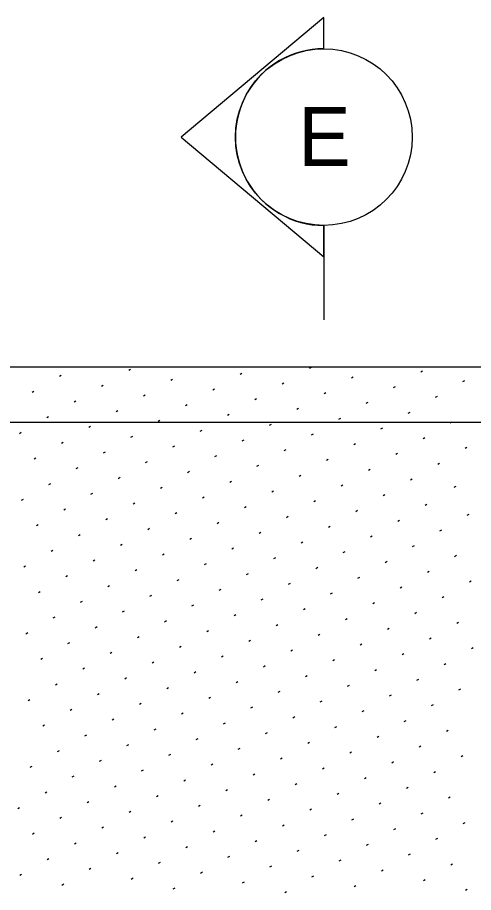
# Model space of a CAD drawing. Extents: x 99862 to 104211, y 98939 to 105076.
# Drawn here: x 101684.2 to 101839, y 104085.1 to 104382.1 of the extents above; entities that cross this region are included whole.
import ezdxf

# ---------------------------------------------------------------- set-up
doc = ezdxf.new("R2010")
doc.units = 0
for name, color, linetype in [('Level 1', 7, 'Continuous'), ('Level 20', 7, 'Continuous'), ('Level 3', 7, 'Continuous'), ('Level 6', 7, 'Continuous'), ('Level 9', 7, 'Continuous')]:
    doc.layers.add(name, color=color, linetype=linetype)

msp = doc.modelspace()

# ---------------------------------------------------------------- linework, layer by layer
at = {"layer": 'Level 1'}
msp.add_line((101394.64, 104263.53), (102106.49, 104263.53), dxfattribs=at)
at = {"layer": 'Level 3'}
for p, q in [((101783.3, 104263.12), (101783.9, 104263.47)), ((101698.42, 104260.31), (101699.03, 104260.66)), ((101721.96, 104262.35), (101722.56, 104262.7)), ((101759.76, 104261.08), (101760.37, 104261.43)), ((101797.56, 104259.81), (101798.17, 104260.16)), ((101821.1, 104261.85), (101821.7, 104262.2)), ((101712.69, 104257), (101713.3, 104257.35)), ((101736.22, 104259.04), (101736.83, 104259.39)), ((101774.03, 104257.77), (101774.63, 104258.12)), ((101811.83, 104256.5), (101812.44, 104256.85)), ((101835.37, 104258.54), (101835.97, 104258.89)), ((101689.15, 104254.96), (101689.76, 104255.31)), ((101726.96, 104253.69), (101727.56, 104254.04)), ((101750.49, 104255.73), (101751.1, 104256.08)), ((101788.3, 104254.46), (101788.9, 104254.81)), ((101703.42, 104251.65), (101704.03, 104252)), ((101764.76, 104252.42), (101765.37, 104252.77)), ((101802.56, 104251.15), (101803.17, 104251.5)), ((101826.1, 104253.19), (101826.7, 104253.54)), ((101717.69, 104248.34), (101718.3, 104248.69)), ((101741.22, 104250.38), (101741.83, 104250.73)), ((101779.03, 104249.11), (101779.63, 104249.46)), ((101816.83, 104247.84), (101817.44, 104248.19)), ((101694.15, 104246.3), (101694.76, 104246.65)), ((101731.96, 104245.03), (101732.56, 104245.38)), ((101755.49, 104247.07), (101756.1, 104247.42)), ((101793.3, 104245.8), (101793.9, 104246.15)), ((101708.42, 104242.99), (101709.03, 104243.34)), ((101746.22, 104241.72), (101746.83, 104242.07)), ((101769.76, 104243.76), (101770.37, 104244.11)), ((101807.56, 104242.49), (101808.17, 104242.84)), ((101831.1, 104244.53), (101831.7, 104244.88)), ((101684.89, 104240.95), (101685.49, 104241.3)), ((101722.69, 104239.68), (101723.3, 104240.03)), ((101784.03, 104240.45), (101784.63, 104240.8)), ((101821.83, 104239.18), (101822.44, 104239.53)), ((101699.15, 104237.64), (101699.76, 104237.99)), ((101736.96, 104236.37), (101737.56, 104236.72)), ((101760.49, 104238.41), (101761.1, 104238.76)), ((101798.3, 104237.14), (101798.9, 104237.49)), ((101836.1, 104235.87), (101836.7, 104236.22)), ((101713.42, 104234.33), (101714.03, 104234.68)), ((101751.22, 104233.06), (101751.83, 104233.41)), ((101774.76, 104235.1), (101775.37, 104235.45)), ((101812.56, 104233.83), (101813.17, 104234.18)), ((101689.89, 104232.29), (101690.49, 104232.64)), ((101727.69, 104231.02), (101728.3, 104231.37)), ((101765.49, 104229.75), (101766.1, 104230.1)), ((101789.03, 104231.79), (101789.63, 104232.14)), ((101826.83, 104230.52), (101827.44, 104230.87)), ((101704.15, 104228.98), (101704.76, 104229.33)), ((101741.96, 104227.71), (101742.56, 104228.06)), ((101803.3, 104228.48), (101803.9, 104228.83)), ((101718.42, 104225.67), (101719.03, 104226.02)), ((101756.22, 104224.4), (101756.83, 104224.75)), ((101779.76, 104226.44), (101780.37, 104226.79)), ((101817.56, 104225.17), (101818.17, 104225.52)), ((101694.89, 104223.62), (101695.49, 104223.97)), ((101732.69, 104222.36), (101733.3, 104222.71)), ((101770.49, 104221.09), (101771.1, 104221.44)), ((101794.03, 104223.13), (101794.63, 104223.48)), ((101832.46, 104222.7), (101833.07, 104223.05)), ((101685.62, 104218.27), (101686.22, 104218.62)), ((101709.15, 104220.32), (101709.76, 104220.67)), ((101746.96, 104219.05), (101747.56, 104219.4)), ((101808.3, 104219.82), (101808.9, 104220.17)), ((101699.89, 104214.96), (101700.49, 104215.31)), ((101723.42, 104217.01), (101724.03, 104217.36)), ((101761.22, 104215.74), (101761.83, 104216.09)), ((101784.76, 104217.78), (101785.37, 104218.13)), ((101822.56, 104216.51), (101823.17, 104216.86)), ((101737.69, 104213.7), (101738.3, 104214.05)), ((101775.49, 104212.43), (101776.1, 104212.78)), ((101799.03, 104214.47), (101799.63, 104214.82)), ((101836.83, 104213.2), (101837.44, 104213.55)), ((101690.62, 104209.61), (101691.22, 104209.96)), ((101714.15, 104211.65), (101714.76, 104212)), ((101751.96, 104210.39), (101752.56, 104210.74)), ((101789.76, 104209.12), (101790.37, 104209.47)), ((101813.3, 104211.16), (101813.9, 104211.51)), ((101704.89, 104206.3), (101705.49, 104206.65)), ((101728.42, 104208.35), (101729.03, 104208.7)), ((101766.22, 104207.08), (101766.83, 104207.43)), ((101827.56, 104207.85), (101828.17, 104208.2)), ((101742.69, 104205.04), (101743.3, 104205.39)), ((101780.49, 104203.77), (101781.1, 104204.12)), ((101804.03, 104205.81), (101804.63, 104206.16)), ((101695.62, 104200.95), (101696.22, 104201.3)), ((101719.15, 104202.99), (101719.76, 104203.34)), ((101756.96, 104201.73), (101757.56, 104202.08)), ((101794.76, 104200.46), (101795.37, 104200.81)), ((101818.3, 104202.5), (101818.9, 104202.85)), ((101709.89, 104197.64), (101710.49, 104197.99)), ((101733.42, 104199.69), (101734.03, 104200.04)), ((101771.22, 104198.42), (101771.83, 104198.77)), ((101809.03, 104197.15), (101809.63, 104197.5)), ((101832.56, 104199.19), (101833.17, 104199.54)), ((101686.35, 104195.6), (101686.96, 104195.95)), ((101724.15, 104194.33), (101724.76, 104194.68)), ((101747.69, 104196.38), (101748.3, 104196.73)), ((101785.49, 104195.11), (101786.1, 104195.46)), ((101700.62, 104192.29), (101701.22, 104192.64)), ((101761.96, 104193.07), (101762.56, 104193.42)), ((101799.76, 104191.8), (101800.37, 104192.15)), ((101823.3, 104193.84), (101823.9, 104194.19)), ((101714.89, 104188.98), (101715.49, 104189.33)), ((101738.42, 104191.02), (101739.03, 104191.37)), ((101776.22, 104189.76), (101776.83, 104190.11)), ((101814.03, 104188.49), (101814.63, 104188.84)), ((101837.56, 104190.53), (101838.17, 104190.88)), ((101691.35, 104186.94), (101691.96, 104187.29)), ((101729.15, 104185.67), (101729.76, 104186.02)), ((101752.69, 104187.72), (101753.3, 104188.07)), ((101790.49, 104186.45), (101791.1, 104186.8)), ((101828.3, 104185.18), (101828.9, 104185.53)), ((101705.62, 104183.63), (101706.22, 104183.98)), ((101743.42, 104182.36), (101744.03, 104182.71)), ((101766.96, 104184.41), (101767.56, 104184.76)), ((101804.76, 104183.14), (101805.37, 104183.49)), ((101719.89, 104180.32), (101720.49, 104180.67)), ((101781.22, 104181.1), (101781.83, 104181.45)), ((101819.03, 104179.83), (101819.63, 104180.18)), ((101696.35, 104178.28), (101696.96, 104178.63)), ((101734.15, 104177.01), (101734.76, 104177.36)), ((101757.69, 104179.06), (101758.3, 104179.41)), ((101795.49, 104177.79), (101796.1, 104178.14)), ((101833.3, 104176.52), (101833.9, 104176.87)), ((101710.62, 104174.97), (101711.22, 104175.32)), ((101748.42, 104173.7), (101749.03, 104174.05)), ((101771.96, 104175.75), (101772.56, 104176.1)), ((101809.76, 104174.48), (101810.37, 104174.83)), ((101687.08, 104172.93), (101687.69, 104173.28)), ((101724.89, 104171.66), (101725.49, 104172.01)), ((101762.69, 104170.39), (101763.3, 104170.74)), ((101786.22, 104172.44), (101786.83, 104172.79)), ((101824.03, 104171.17), (101824.63, 104171.52)), ((101701.35, 104169.62), (101701.96, 104169.97)), ((101739.15, 104168.35), (101739.76, 104168.7)), ((101800.49, 104169.13), (101801.1, 104169.48)), ((101838.3, 104167.86), (101838.9, 104168.21)), ((101715.62, 104166.31), (101716.22, 104166.66)), ((101753.42, 104165.04), (101754.03, 104165.39)), ((101776.96, 104167.09), (101777.56, 104167.44)), ((101814.76, 104165.82), (101815.37, 104166.17)), ((101692.08, 104164.27), (101692.69, 104164.62)), ((101729.89, 104163), (101730.49, 104163.35)), ((101767.69, 104161.73), (101768.3, 104162.08)), ((101791.22, 104163.78), (101791.83, 104164.13)), ((101829.03, 104162.51), (101829.63, 104162.86)), ((101706.35, 104160.96), (101706.96, 104161.31)), ((101744.15, 104159.69), (101744.76, 104160.04)), ((101805.49, 104160.47), (101806.1, 104160.82)), ((101697.08, 104155.61), (101697.69, 104155.96)), ((101720.62, 104157.65), (101721.22, 104158)), ((101758.42, 104156.38), (101759.03, 104156.73)), ((101781.96, 104158.43), (101782.56, 104158.78)), ((101819.76, 104157.16), (101820.37, 104157.51)), ((101734.89, 104154.34), (101735.49, 104154.69)), ((101772.69, 104153.07), (101773.3, 104153.42)), ((101796.22, 104155.12), (101796.83, 104155.47)), ((101834.03, 104153.85), (101834.63, 104154.2)), ((101687.82, 104150.26), (101688.42, 104150.61)), ((101711.35, 104152.3), (101711.96, 104152.65)), ((101749.15, 104151.03), (101749.76, 104151.38)), ((101786.96, 104149.76), (101787.56, 104150.11)), ((101810.49, 104151.81), (101811.1, 104152.16)), ((101702.08, 104146.95), (101702.69, 104147.3)), ((101725.62, 104148.99), (101726.22, 104149.34)), ((101763.42, 104147.72), (101764.03, 104148.07)), ((101824.76, 104148.5), (101825.37, 104148.85)), ((101716.35, 104143.64), (101716.96, 104143.99)), ((101739.89, 104145.68), (101740.49, 104146.03)), ((101777.69, 104144.41), (101778.3, 104144.76)), ((101801.22, 104146.46), (101801.83, 104146.81)), ((101692.82, 104141.6), (101693.42, 104141.95)), ((101754.15, 104142.37), (101754.76, 104142.72)), ((101791.96, 104141.1), (101792.56, 104141.45)), ((101815.49, 104143.15), (101816.1, 104143.5)), ((101707.08, 104138.29), (101707.69, 104138.64)), ((101730.62, 104140.33), (101731.22, 104140.68)), ((101768.42, 104139.06), (101769.03, 104139.41)), ((101806.22, 104137.79), (101806.83, 104138.14)), ((101829.76, 104139.84), (101830.37, 104140.19)), ((101721.35, 104134.98), (101721.96, 104135.33)), ((101744.89, 104137.02), (101745.49, 104137.37)), ((101782.69, 104135.75), (101783.3, 104136.1)), ((101697.82, 104132.94), (101698.42, 104133.29)), ((101759.15, 104133.71), (101759.76, 104134.06)), ((101796.96, 104132.44), (101797.56, 104132.79)), ((101820.49, 104134.49), (101821.1, 104134.84)), ((101712.08, 104129.63), (101712.69, 104129.98)), ((101735.62, 104131.67), (101736.22, 104132.02)), ((101773.42, 104130.4), (101774.03, 104130.75)), ((101811.22, 104129.13), (101811.83, 104129.48)), ((101834.76, 104131.18), (101835.37, 104131.53)), ((101688.55, 104127.59), (101689.15, 104127.94)), ((101726.35, 104126.32), (101726.96, 104126.67)), ((101749.89, 104128.36), (101750.49, 104128.71)), ((101787.69, 104127.09), (101788.3, 104127.44)), ((101825.49, 104125.83), (101826.1, 104126.18)), ((101702.82, 104124.28), (101703.42, 104124.63)), ((101740.62, 104123.01), (101741.22, 104123.36)), ((101764.15, 104125.05), (101764.76, 104125.4)), ((101801.96, 104123.78), (101802.56, 104124.13)), ((101717.08, 104120.97), (101717.69, 104121.32)), ((101778.42, 104121.74), (101779.03, 104122.09)), ((101816.22, 104120.47), (101816.83, 104120.82)), ((101693.55, 104118.93), (101694.15, 104119.28)), ((101731.35, 104117.66), (101731.96, 104118.01)), ((101754.89, 104119.7), (101755.49, 104120.05)), ((101792.69, 104118.43), (101793.3, 104118.78)), ((101830.49, 104117.16), (101831.1, 104117.51)), ((101707.82, 104115.62), (101708.42, 104115.97)), ((101745.62, 104114.35), (101746.22, 104114.7)), ((101769.15, 104116.39), (101769.76, 104116.74)), ((101806.96, 104115.12), (101807.56, 104115.47)), ((101684.28, 104113.58), (101684.89, 104113.93)), ((101722.08, 104112.31), (101722.69, 104112.66)), ((101759.89, 104111.04), (101760.49, 104111.39)), ((101783.42, 104113.08), (101784.03, 104113.43)), ((101821.22, 104111.81), (101821.83, 104112.16)), ((101698.55, 104110.27), (101699.15, 104110.62)), ((101736.35, 104109), (101736.96, 104109.35)), ((101797.69, 104109.77), (101798.3, 104110.12)), ((101835.49, 104108.5), (101836.1, 104108.85)), ((101712.82, 104106.96), (101713.42, 104107.31)), ((101750.62, 104105.69), (101751.22, 104106.04)), ((101774.15, 104107.73), (101774.76, 104108.08)), ((101811.96, 104106.46), (101812.56, 104106.81)), ((101689.28, 104104.92), (101689.89, 104105.27)), ((101727.08, 104103.65), (101727.69, 104104)), ((101764.89, 104102.38), (101765.49, 104102.73)), ((101788.42, 104104.42), (101789.03, 104104.77)), ((101826.22, 104103.15), (101826.83, 104103.5)), ((101703.55, 104101.61), (101704.15, 104101.96)), ((101741.35, 104100.34), (101741.96, 104100.69)), ((101779.15, 104099.07), (101779.76, 104099.42)), ((101802.69, 104101.11), (101803.3, 104101.46)), ((101694.28, 104096.26), (101694.89, 104096.61)), ((101717.82, 104098.3), (101718.42, 104098.65)), ((101755.62, 104097.03), (101756.22, 104097.38)), ((101816.96, 104097.8), (101817.56, 104098.15)), ((101732.08, 104094.99), (101732.69, 104095.34)), ((101769.89, 104093.72), (101770.49, 104094.07)), ((101793.42, 104095.76), (101794.03, 104096.11)), ((101831.22, 104094.49), (101831.83, 104094.84)), ((101685.01, 104090.91), (101685.62, 104091.26)), ((101708.55, 104092.95), (101709.15, 104093.3)), ((101746.35, 104091.68), (101746.96, 104092.03)), ((101784.15, 104090.41), (101784.76, 104090.76)), ((101807.69, 104092.45), (101808.3, 104092.8)), ((101699.28, 104087.6), (101699.89, 104087.95)), ((101722.82, 104089.64), (101723.42, 104089.99)), ((101760.62, 104088.37), (101761.22, 104088.72)), ((101821.96, 104089.14), (101822.56, 104089.49)), ((101737.08, 104086.33), (101737.69, 104086.68)), ((101774.89, 104085.06), (101775.49, 104085.41)), ((101798.42, 104087.1), (101799.03, 104087.45)), ((101836.22, 104085.83), (101836.83, 104086.18))]:
    msp.add_line(p, q, dxfattribs=at)
at = {"layer": 'Level 6'}
msp.add_line((102647.84, 104244.65), (101394.64, 104244.65), dxfattribs=at)
at = {"layer": 'Level 9'}
for p, q in [((101788.17, 104382.13), (101739.71, 104341.53)), ((101788.17, 104371.53), (101788.17, 104382.13)), ((101739.71, 104341.53), (101788.17, 104300.93)), ((101788.17, 104300.93), (101788.17, 104311.53)), ((101788.17, 104311.53), (101788.17, 104279.53))]:
    msp.add_line(p, q, dxfattribs=at)
msp.add_circle((101788.17, 104341.53), 30, dxfattribs=at)
msp.add_arc((101788.17, 104341.53), 30, 89.9978, 270.0022, dxfattribs=at)

# ---------------------------------------------------------------- texts
at = {"layer": 'Level 20'}
msp.add_text('E', height=20, dxfattribs=at).set_placement((101779.47, 104331.71))

doc.saveas('drawing.dxf')
